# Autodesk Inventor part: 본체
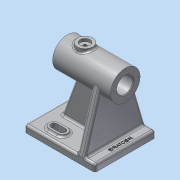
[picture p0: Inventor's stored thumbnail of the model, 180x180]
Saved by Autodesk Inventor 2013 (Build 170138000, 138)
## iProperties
Created: 2019-10
Part Number: 본체
Material: 알루미늄 6061
Document SubType Name: Modeling
Designer: Administrator
Density: 2.71 g/cm^3
Mass: 615.452 g
Surface Area: 534.822 cm^2
Volume: 227.104 cm^3
Author: Administrator
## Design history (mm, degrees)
sketch "스케치1"
  geometry: L1 (-50, 43)-(50, 43); L2 (50, 43)-(50, -43); L3 (50, -43)-(-50, -43); L4 (-50, -43)-(-50, 43); 1 further point
  constraints: 8 end point, 2 parallel, 1 horizontal, 1 perpendicular
  dimensions: "d0" = 100 distance of L1.start L1.end; "d2" = 86 distance of L1.end L2.end; "d6" = 50 distance from line of L2 point (0, 0); "d7" = 43 distance from line of point (0, 0) L1
extrude "돌출1" new body sketch "스케치1" distance "d8" = 10; taper "d9" = 0 deg
sketch "스케치2"
  geometry: L1 (-50, 43)-(-50, -43) reference; L2 (50, -43)-(50, 43) reference; L3 (-24, 34)-(-12, 34); L4 (-12, 20)-(-24, 20); A1 r 7 centre (-12, 27) between (-12, 20) and (-12, 34); A2 r 7 centre (-24, 27) between (-24, 34) and (-24, 20); 1 further point
  constraints: 4 end point, 4 point on circle, 4 tangent, 2 centre point, 1 parallel, 1 perpendicular
  dimensions: "d10" = 12 distance of A1.centre A2.centre; "d12" = 14 distance between parallel lines of L4 L3; "d13" = 26 distance from line of L1 A2.centre; "d14" = 27 vertical distance of A2.centre point (0, 0)
extrude "돌출2" join sketch "스케치2" distance "d15" = 3; taper "d16" = 0 deg
sketch "스케치3"
  geometry: L1 (-24, 20)-(-12, 20) reference; L2 (-24, 31.5)-(-12, 31.5); L3 (-12, 22.5)-(-24, 22.5); A1 r 7 centre (-24, 27) between (-24, 34) and (-24, 20) reference; A2 r 7 centre (-12, 27) between (-12, 20) and (-12, 34) reference; A3 r 4.5 centre (-12, 27) between (-12, 22.5) and (-12, 31.5); A4 r 4.5 centre (-24, 27) between (-24, 31.5) and (-24, 22.5); 1 further point
  constraints: 4 end point, 4 point on circle, 4 tangent, 2 centre point, 2 coincident, 2 parallel
  dimensions: "d17" = 9 distance between parallel lines of L3 L2
extrude "돌출3" cut sketch "스케치3" distance "d19" = 13; taper "d20" = 0 deg
sketch "스케치5"
  geometry: L1 (50, 10)-(-50, 10) reference; L2 (-50, 86)-(32, 86); L3 (-50, 97.5)-(-30, 97.5); L4 (-50, 97.5)-(-50, 107); L5 (-50, 107)-(32, 107); L6 (32, 107)-(32, 100.5); L7 (-30, 97.5)-(-30, 100.5); L8 (-30, 100.5)-(32, 100.5); L9 (50, 0)-(-50, 0) reference; 1 further point
  constraints: 14 end point, 3 vertical alignment, 2 parallel, 1 horizontal, 1 perpendicular, 1 vertical
  dimensions: "d22" = 82 distance of L2.start L2.end; "d28" = 23 diameter of L3 L2; "d30" = 29 diameter of L8 L2; "d31" = 42 diameter of L5 L2; "d72" = 86 distance between parallel lines of L9 L2; "d103" = 62 distance between parallel lines of L7 L6
revolve "회전1" sketch "스케치5" stored, may be unused: angle "d32" = 90 deg
sketch "스케치6"
  geometry: C1 r 21 at (0, 0) reference; 5 further points
  constraints: 2 horizontal alignment, 2 vertical alignment
  dimensions: "d33" = 18 distance of C1.centre point (-18, 0); "d34" = 36 distance of point (18, 0) point (-18, 0); "d35" = 18 distance of point (0, 18) C1.centre; "d36" = 36 distance of point (0, -18) point (0, 18)
hole "구멍1" sketch "스케치6" at (-18, 0), (0, 18), (18, 0), (0, -18) diameter "d37" = 2.459; stored, may be unused: countersink angle "d41" = 90 deg, drill point angle "d43" = 118 deg; dims "d38" = 8, "d39" = 4, "d40" = 2, "d42" = 10
sketch "스케치7"
  geometry: C1 r 14.5 at (0, 0) reference; 5 further points
  constraints: 2 horizontal alignment, 2 vertical alignment
  dimensions: "d44" = 18 distance of C1.centre point (18, 0); "d45" = 36 distance of point (-18, 0) point (18, 0); "d46" = 18 distance of point (0, -18) C1.centre; "d47" = 36 distance of point (0, -18) point (0, 18)
hole "구멍2" sketch "스케치7" at (18, 0), (0, -18), (-18, 0), (0, 18) diameter "d48" = 2.459; stored, may be unused: countersink angle "d52" = 90 deg, drill point angle "d54" = 118 deg; dims "d49" = 8, "d50" = 4, "d51" = 2, "d53" = 10
node "작업 평면3"
sketch "스케치10"
  geometry: L1 (43, 10)-(-43, 10) reference; L2 (-43, 10)-(-21, 86); L3 (43, 10)-(21, 86); L4 (-43, 10)-(43, 10); A1 r 21 centre (0, 86) between (-21, 86) and (21, 86) reference; A2 r 21 centre (0, 86) between (-21, 86) and (21, 86); 1 further point
  constraints: 6 end point, 4 point on circle, 2 horizontal alignment, 1 centre point, 1 coincident, 1 collinear
extrude "돌출4" join sketch "스케치10" distance "d61" = 10; taper "d62" = 0 deg
sketch "스케치11"
  geometry: L1 (-50, 65)-(32, 65) reference; L2 (50, 10)-(-25, 10) reference; L3 (14.982, 65)-(35, 10); L4 (50, 0)-(50, 10) reference; 1 further point
  constraints: 2 end point, 2 point on line
  dimensions: "d63" = 15 distance from line of L3.end L4; "d64" = 70 deg angle of L2 L3
feature "리브1" sketch "스케치11" dims "d65" = 1, "d66" = 10, "d67" = 0, "d68" = 0, "d69" = 1, "d70" = 1
sketch "스케치12"
  geometry: C1 r 21 at (0, 86) reference; 1 further point
node "작업 평면5"
sketch "스케치13"
  geometry: L1 (-32, 21)-(-32, -21) reference; C1 r 11 at (-7, 0); 1 further point
  constraints: 1 centre point, 1 horizontal alignment
  dimensions: "d76" = 25 distance from line of L1 C1.centre; "d77" = 22 diameter of C1
extrude "돌출5" join sketch "스케치13" stored distance "d78" = 10; taper "d79" = 0 deg
sketch "스케치14"
  geometry: C1 r 11 at (0, 0) reference; C2 r 7 at (0, 0); 1 further point
  constraints: 1 centre point, 1 coincident
  dimensions: "d80" = 14 diameter of C2
extrude "돌출6" cut sketch "스케치14" distance "d82" = 4; taper "d83" = 0 deg
sketch "스케치15"
  geometry: 3 further points
  constraints: 1 coincident, 1 horizontal alignment
hole "구멍3" sketch "스케치15" at (0, 0) diameter "d84" = 4.917; stored, may be unused: countersink angle "d88" = 90 deg, drill point angle "d90" = 0 deg; dims "d85" = 8, "d86" = 4, "d87" = 2, "d89" = 24
sketch "스케치17"
  geometry: L1 (50, -43)-(50, 43) reference; L2 (35, -43)-(50, -43) reference; 2 further points
  constraints: 1 other
  dimensions: "d91" = 43 distance from line of L2 point (43, 0); "d92" = 7 distance from line of L1 point (43, 0)
feature "엠보싱1" sketch "스케치17" dims "d0" = 100, "d2" = 86, "d6" = 50, "d7" = 43, "d93" = 0.5, "d94" = 0
chamfer "모따기1" distance "d95" = 1; stored, may be unused: second distance "d96" = 2, angle "d97" = 45 deg
fillet "모깎기1" dims "d98" = 3
fillet "모깎기2" dims "d99" = 3
fillet "모깎기3" dims "d100" = 3
fillet "모깎기4" dims "d101" = 3
fillet "모깎기5" dims "d102" = 3
node "솔리드1"
mirror "대칭1"
other parameters: "d59" = 35
